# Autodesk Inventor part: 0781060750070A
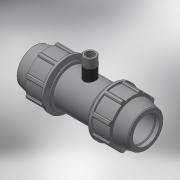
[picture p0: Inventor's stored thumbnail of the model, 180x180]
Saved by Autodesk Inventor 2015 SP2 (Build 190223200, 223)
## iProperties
Created: 2017-02
Part Number: 0781060750070A
Material: Generic
Description: PLASSON COUPLER WITH RISER 75-3/4"
Document SubType Name: Modeling
Designer: KIM
Mass: 1772.99 g
Surface Area: 2354.31 cm^2
Volume: 1772.99 cm^3
Density: 1 g/cm^3
Appearance: Default
Author: KIM
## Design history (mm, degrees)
derived "87810.ipt"
feature "Solid1::87810.ipt"
feature "Solid2::87810.ipt"
tag "TaggingFeature1"
body "Solid1"
other parameters: "d2" = 75, "d4" = 13.04167, "d5" = 37.56, "d7" = 134, "d11" = 5.21667, "d13" = 120 deg, "d14" = 97.5, "d15" = 12 deg, "d16" = 116.58, "d18" = 3.75, "d19" = 35 deg, "d20" = 17.5 deg, "d21" = 124.62, "d23" = 0, "d25" = 360 deg, "d27" = 2.68, "d33" = 1.5, "d42" = 56.34, "d43" = 4.02, "d46" = 2.25, "d68" = 5.21667, "d72" = 105, "d73" = 26.441, "d74" = 18, "d76" = 18.5087, "d77" = 21.6, "d80" = 0.79323, "d91" = 100.5, "d93" = 132, "d95" = 67.5, "d99" = 313, "d101" = 0, "d103" = 0, "d105" = 0, "d106" = 26.96982, "d107" = 6.26, "d108" = 0, "d_" = 75, "E_" = 134, "A_" = 105, "l_" = 132, "l_2" = 18, "H_" = 313, "R_" = 26.441
